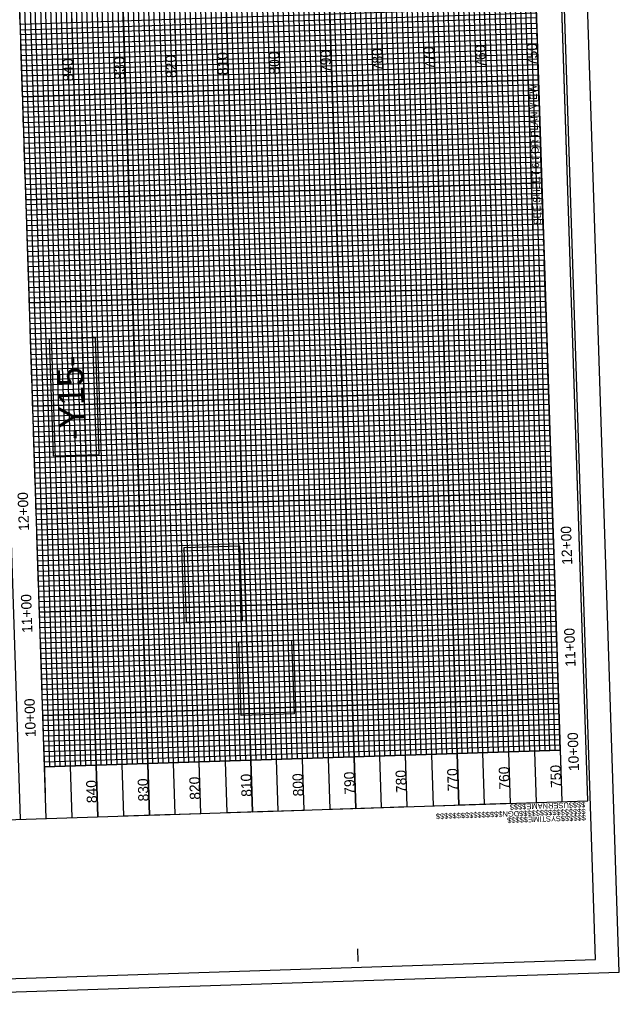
# Model space of a CAD drawing. Extents: x 1627314 to 1628469, y 762309 to 764245.
# Drawn here: x 1627888 to 1628469, y 762309 to 763268 of the extents above; entities that cross this region are included whole.
import ezdxf

# ---------------------------------------------------------------- set-up
doc = ezdxf.new("R2010")
doc.units = 0
for name, color, linetype in [('Exist Vertical Profile Horizontal Axis Label Major', 7, 'Continuous'), ('Exist Vertical Profile Vertical Axis Label', 7, 'Continuous'), ('Prop DSN Text', 7, 'Continuous'), ('Prop Grid Mask', 7, 'Continuous'), ('Sheet Data Field CELL', 7, 'Continuous'), ('Sheet DOT Grid CELL', 7, 'Continuous'), ('Sheet Layout Profile Border Port 2', 7, 'Continuous'), ('Sheet Plot Border Inside CELL', 7, 'Continuous'), ('Sheet Plot Border Outside CELL', 7, 'Continuous'), ('Sheet Profile CELL', 7, 'Continuous'), ('Sheet Profile Grid Major CELL', 7, 'Continuous'), ('Sheet Profile Grid Middle CELL', 7, 'Continuous'), ('Sheet Profile Grid Minor CELL', 7, 'Continuous')]:
    doc.layers.add(name, color=color, linetype=linetype)

msp = doc.modelspace()

# ---------------------------------------------------------------- linework, layer by layer
at = {"layer": 'Prop Grid Mask'}
for points in [[(1627891.16, 763193.83), (1627889.52, 763243.8), (1628389.25, 763260.15), (1628390.89, 763210.18)], [(1628380.89, 763209.85), (1628385.63, 763064.93), (1628395.63, 763065.25), (1628390.89, 763210.18)], [(1627965.43, 762847.15), (1627961.73, 762960.18), (1627917.01, 762958.71), (1627920.71, 762845.69)], [(1628050.07, 762684.01), (1628047.69, 762756.81), (1628101.34, 762758.56), (1628103.72, 762685.77)], [(1628102.83, 762594.05), (1628100.49, 762665.48), (1628151.84, 762667.16), (1628154.18, 762595.73)]]:
    msp.add_lwpolyline(points, close=True, dxfattribs=at)
at = {"layer": 'Sheet DOT Grid CELL'}
for p, q in [((1628263.85, 762505.65), (1628214.82, 764004.73)), ((1628313.83, 762507.28), (1628264.79, 764006.37)), ((1628363.8, 762508.92), (1628314.77, 764008)), ((1627964.01, 762495.84), (1627914.98, 763994.92)), ((1628013.99, 762497.47), (1627964.95, 763996.56)), ((1628063.96, 762499.11), (1628014.93, 763998.19)), ((1628113.93, 762500.74), (1628064.9, 763999.83)), ((1628163.91, 762502.38), (1628114.87, 764001.46)), ((1628213.88, 762504.01), (1628164.85, 764003.1)), ((1627914.04, 762494.2), (1627865.01, 763993.29)), ((1627889.52, 763243.8), (1628389.25, 763260.15)), ((1627891.16, 763193.83), (1628390.89, 763210.18)), ((1627892.79, 763143.86), (1628392.52, 763160.2)), ((1627894.43, 763093.88), (1628394.16, 763110.23)), ((1627896.06, 763043.91), (1628395.79, 763060.26)), ((1627897.69, 762993.94), (1628397.43, 763010.28)), ((1627899.33, 762943.96), (1628399.06, 762960.31)), ((1627900.96, 762893.99), (1628400.7, 762910.34)), ((1627902.6, 762844.02), (1628402.33, 762860.36)), ((1627904.23, 762794.04), (1628403.97, 762810.39)), ((1627905.87, 762744.07), (1628405.6, 762760.42)), ((1627907.5, 762694.1), (1628407.24, 762710.44)), ((1627909.14, 762644.12), (1628408.87, 762660.47)), ((1627910.77, 762594.15), (1628410.5, 762610.5)), ((1627912.41, 762544.18), (1628412.14, 762560.52))]:
    msp.add_line(p, q, dxfattribs=at)
at = {"layer": 'Sheet Layout Profile Border Port 2'}
msp.add_lwpolyline([(1627912.41, 762544.18), (1627866.64, 763943.43), (1628366.37, 763959.78), (1628412.14, 762560.52)], close=True, dxfattribs=at)
at = {"layer": 'Sheet Plot Border Inside CELL'}
msp.add_lwpolyline([(1628446.34, 762357.53), (1628391.86, 764023.14), (1627337.33, 763988.65), (1627391.81, 762323.04)], close=True, dxfattribs=at)
at = {"layer": 'Sheet Plot Border Outside CELL'}
msp.add_lwpolyline([(1628469.21, 762345.27), (1628413.63, 764044.37), (1627314.22, 764008.4), (1627369.79, 762309.31)], close=True, dxfattribs=at)
at = {"layer": 'Sheet Profile CELL'}
for p, q in [((1628364.74, 764009.75), (1628413.77, 762510.55)), ((1628438.76, 762511.37), (1628389.72, 764010.57)), ((1627889.05, 762493.39), (1627840.02, 763992.59)), ((1627914.04, 762494.2), (1627865, 763993.4)), ((1628438.76, 762511.37), (1628438.76, 762511.37)), ((1628438.76, 762511.37), (1628438.76, 762511.37)), ((1628438.76, 762511.37), (1628438.76, 762511.37)), ((1628438.76, 762511.37), (1628438.76, 762511.37)), ((1628438.76, 762511.37), (1628438.76, 762511.37)), ((1628438.76, 762511.37), (1628438.76, 762511.37)), ((1628438.76, 762511.37), (1628438.76, 762511.37)), ((1628216.24, 762355.51), (1628215.83, 762368))]:
    msp.add_line(p, q, dxfattribs=at)
msp.add_lwpolyline([(1627340.28, 763976.24), (1627389.32, 762477.04), (1628438.76, 762511.37), (1628389.72, 764010.57)], close=True, dxfattribs=at)
msp.add_lwpolyline([(1628437.53, 762548.85), (1628437.53, 762548.85)], dxfattribs=at)
at = {"layer": 'Sheet Profile Grid Major CELL'}
for p, q in [((1627891.16, 763193.83), (1627889.52, 763243.8)), ((1627894.43, 763093.88), (1627892.79, 763143.86)), ((1627897.69, 762993.94), (1627896.06, 763043.91)), ((1628413.77, 762510.55), (1628413.77, 762510.55))]:
    msp.add_line(p, q, dxfattribs=at)
for points in [[(1628164.84, 764003.21), (1628213.88, 762504.01), (1628263.85, 762505.65), (1628214.82, 764004.85)], [(1628264.79, 764006.48), (1628313.83, 762507.28), (1628313.83, 762507.28), (1628363.8, 762508.92), (1628314.76, 764008.11)], [(1628364.74, 764009.75), (1628413.77, 762510.55)], [(1627914.98, 763995.04), (1627964.01, 762495.84)], [(1627964.95, 763996.67), (1628013.99, 762497.47), (1628063.96, 762499.11), (1628014.92, 763998.31)], [(1628064.9, 763999.94), (1628113.93, 762500.74), (1628163.91, 762502.38), (1628114.87, 764001.58)], [(1627912.41, 762544.18), (1628412.14, 762560.52), (1628410.5, 762610.5), (1627910.77, 762594.15), (1627909.14, 762644.12), (1628408.87, 762660.47), (1628407.24, 762710.44), (1627907.5, 762694.1), (1627905.87, 762744.07), (1628405.6, 762760.42), (1628403.97, 762810.39), (1627904.23, 762794.04), (1627902.6, 762844.02), (1628402.33, 762860.36), (1628400.7, 762910.34), (1627900.96, 762893.99), (1627899.33, 762943.96), (1628399.06, 762960.31), (1628397.43, 763010.28), (1627897.69, 762993.94), (1627896.06, 763043.91), (1628395.79, 763060.26), (1628394.16, 763110.23), (1627894.43, 763093.88), (1627892.79, 763143.86), (1628392.52, 763160.2), (1628390.89, 763210.18), (1627891.16, 763193.83), (1627889.52, 763243.8), (1628389.25, 763260.15), (1628387.62, 763310.12)]]:
    msp.add_lwpolyline(points, dxfattribs=at)
at = {"layer": 'Sheet Profile Grid Middle CELL'}
for points in [[(1628139.86, 764002.39), (1628188.89, 762503.2), (1628238.87, 762504.83), (1628189.83, 764004.03)], [(1628239.8, 764005.66), (1628288.84, 762506.46), (1628338.81, 762508.1), (1628289.78, 764007.3)], [(1628339.75, 764008.93), (1628388.79, 762509.73)], [(1627939.03, 762495.02), (1627889.99, 763994.22)], [(1627939.96, 763995.85), (1627989, 762496.66), (1628038.97, 762498.29), (1627989.94, 763997.49)], [(1628039.91, 763999.12), (1628088.95, 762499.93), (1628138.92, 762501.56), (1628089.88, 764000.76)], [(1627913.22, 762519.19), (1627911.59, 762569.16), (1628411.32, 762585.51), (1628409.69, 762635.48), (1627909.95, 762619.14), (1627908.32, 762669.11), (1628408.05, 762685.46), (1628406.42, 762735.43), (1627906.69, 762719.08), (1627905.05, 762769.06), (1628404.78, 762785.4), (1628403.15, 762835.38), (1627903.42, 762819.03), (1627901.78, 762869), (1628401.51, 762885.35), (1628399.88, 762935.32), (1627900.15, 762918.98), (1627898.51, 762968.95), (1628398.24, 762985.3), (1628396.61, 763035.27), (1627896.88, 763018.92), (1627895.24, 763068.9), (1628394.98, 763085.24), (1628393.34, 763135.22), (1628393.34, 763135.22), (1627893.61, 763118.87), (1627891.97, 763168.84), (1628391.71, 763185.19), (1628390.07, 763235.16), (1627890.34, 763218.82), (1627888.7, 763268.79)]]:
    msp.add_lwpolyline(points, dxfattribs=at)
at = {"layer": 'Sheet Profile Grid Minor CELL'}
for p, q in [((1628292.2, 762556.6), (1628246.43, 763955.85)), ((1628251.43, 763956.02), (1628297.2, 762556.76)), ((1628302.2, 762556.93), (1628256.43, 763956.18)), ((1628261.43, 763956.34), (1628307.2, 762557.09)), ((1628317.19, 762557.42), (1628271.42, 763956.67)), ((1628276.42, 763956.83), (1628322.19, 762557.58)), ((1628327.18, 762557.75), (1628281.42, 763957)), ((1628286.41, 763957.16), (1628332.18, 762557.91)), ((1628342.18, 762558.24), (1628296.41, 763957.49)), ((1628301.4, 763957.65), (1628347.17, 762558.4)), ((1628352.17, 762558.56), (1628306.4, 763957.81)), ((1628311.4, 763957.98), (1628357.17, 762558.73)), ((1628367.16, 762559.05), (1628321.39, 763958.3)), ((1628326.39, 763958.47), (1628372.16, 762559.22)), ((1628377.16, 762559.38), (1628331.39, 763958.63)), ((1628336.39, 763958.8), (1628382.16, 762559.54)), ((1628392.15, 762559.87), (1628346.38, 763959.12)), ((1628351.38, 763959.29), (1628397.15, 762560.03)), ((1628402.14, 762560.2), (1628356.37, 763959.45)), ((1628407.14, 762560.36), (1628361.37, 763959.61)), ((1627951.59, 763946.21), (1627997.36, 762546.96)), ((1628002.36, 762547.12), (1627956.59, 763946.37)), ((1627961.59, 763946.54), (1628007.36, 762547.28)), ((1628017.35, 762547.61), (1627971.58, 763946.86)), ((1627976.58, 763947.03), (1628022.35, 762547.77)), ((1628027.34, 762547.94), (1627981.58, 763947.19)), ((1627986.57, 763947.35), (1628032.34, 762548.1)), ((1628042.34, 762548.43), (1627996.57, 763947.68)), ((1628001.56, 763947.84), (1628047.33, 762548.59)), ((1628052.33, 762548.75), (1628006.56, 763948.01)), ((1628011.56, 763948.17), (1628057.33, 762548.92)), ((1628067.32, 762549.25), (1628021.55, 763948.5)), ((1628026.55, 763948.66), (1628072.32, 762549.41)), ((1628077.32, 762549.57), (1628031.55, 763948.82)), ((1628036.55, 763948.99), (1628082.32, 762549.74)), ((1628092.31, 762550.06), (1628046.54, 763949.31)), ((1628051.54, 763949.48), (1628097.31, 762550.23)), ((1628102.3, 762550.39), (1628056.54, 763949.64)), ((1628061.53, 763949.8), (1628107.15, 762550.55)), ((1628117.3, 762550.88), (1628071.53, 763950.13)), ((1628076.52, 763950.3), (1628122.29, 762551.04)), ((1628127.29, 762551.21), (1628081.52, 763950.46)), ((1628086.52, 763950.62), (1628132.29, 762551.37)), ((1628142.28, 762551.7), (1628096.51, 763950.95)), ((1628101.51, 763951.11), (1628147.28, 762551.86)), ((1628152.28, 762552.02), (1628106.51, 763951.28)), ((1628111.51, 763951.44), (1628157.28, 762552.19)), ((1628167.27, 762552.51), (1628121.5, 763951.77)), ((1628126.5, 763951.93), (1628172.27, 762552.68)), ((1628177.26, 762552.84), (1628131.5, 763952.09)), ((1628136.49, 763952.26), (1628182.26, 762553)), ((1628192.26, 762553.33), (1628146.49, 763952.58)), ((1628151.48, 763952.75), (1628197.25, 762553.5)), ((1628202.25, 762553.66), (1628156.48, 763952.91)), ((1628161.48, 763953.07), (1628207.25, 762553.82)), ((1628217.24, 762554.15), (1628171.47, 763953.4)), ((1628176.47, 763953.56), (1628222.24, 762554.31)), ((1628227.24, 762554.48), (1628181.47, 763953.73)), ((1628186.47, 763953.89), (1628232.24, 762554.64)), ((1628242.23, 762554.97), (1628196.46, 763954.22)), ((1628201.46, 763954.38), (1628247.23, 762555.13)), ((1628252.22, 762555.29), (1628206.46, 763954.55)), ((1628211.45, 763954.71), (1628257.22, 762555.46)), ((1628267.22, 762555.78), (1628221.45, 763955.04)), ((1628226.44, 763955.2), (1628272.21, 762555.95)), ((1628277.21, 762556.11), (1628231.44, 763955.36)), ((1628236.44, 763955.53), (1628282.21, 762556.27)), ((1627917.4, 762544.34), (1627871.63, 763943.59)), ((1627876.63, 763943.76), (1627922.4, 762544.5)), ((1627927.4, 762544.67), (1627881.63, 763943.92)), ((1627886.63, 763944.08), (1627932.4, 762544.83)), ((1627942.39, 762545.16), (1627896.62, 763944.41)), ((1627901.62, 763944.57), (1627947.39, 762545.32)), ((1627952.38, 762545.49), (1627906.62, 763944.74)), ((1627911.61, 763944.9), (1627957.38, 762545.65)), ((1627967.38, 762545.98), (1627921.61, 763945.23)), ((1627926.6, 763945.39), (1627972.37, 762546.14)), ((1627977.37, 762546.3), (1627931.6, 763945.55)), ((1627936.6, 763945.72), (1627982.37, 762546.47)), ((1627992.36, 762546.79), (1627946.59, 763946.05))]:
    msp.add_line(p, q, dxfattribs=at)
for points in [[(1628388.6, 763280.14), (1627888.87, 763263.79), (1627888.54, 763273.79)], [(1627895.08, 763073.89), (1628394.81, 763090.24), (1628394.65, 763095.24), (1627894.92, 763078.89), (1627894.75, 763083.89), (1628394.49, 763100.24), (1628394.32, 763105.23), (1627894.59, 763088.89), (1627894.26, 763098.88), (1628393.99, 763115.23), (1628393.83, 763120.22), (1627894.1, 763103.88), (1627893.94, 763108.88), (1628393.67, 763125.22), (1628393.5, 763130.22), (1627893.77, 763113.87), (1627893.44, 763123.87), (1628393.18, 763140.21), (1628393.01, 763145.21), (1627893.28, 763128.87), (1627893.12, 763133.86), (1628392.85, 763150.21), (1628392.69, 763155.21), (1627892.95, 763138.86), (1627892.63, 763148.85), (1628392.36, 763165.2), (1628392.2, 763170.2), (1627892.46, 763153.85), (1627892.3, 763158.85), (1628392.03, 763175.2), (1628391.87, 763180.19), (1627892.14, 763163.85), (1627891.81, 763173.84), (1628391.54, 763190.19), (1628391.38, 763195.18), (1627891.65, 763178.84), (1627891.48, 763183.84), (1628391.22, 763200.18), (1628391.05, 763205.18), (1627891.32, 763188.83), (1627890.99, 763198.83), (1628390.73, 763215.17), (1628390.73, 763215.17), (1628390.56, 763220.17), (1627890.83, 763203.83), (1627890.67, 763208.82), (1628390.4, 763225.17), (1628390.24, 763230.17), (1627890.5, 763213.82), (1627890.18, 763223.81), (1628389.91, 763240.16), (1628389.74, 763245.16), (1627890.01, 763228.81), (1627889.85, 763233.81), (1628389.58, 763250.16), (1628389.42, 763255.15), (1627889.69, 763238.81), (1627889.36, 763248.8), (1628389.09, 763265.15), (1628388.93, 763270.14), (1627889.19, 763253.8), (1627889.03, 763258.8), (1628388.76, 763275.14)], [(1628405.11, 762775.41), (1628404.95, 762780.41), (1627905.21, 762764.06), (1627904.89, 762774.06), (1628404.62, 762790.4), (1628404.46, 762795.4), (1627904.72, 762779.05), (1627904.56, 762784.05), (1628404.29, 762800.4), (1628404.13, 762805.39), (1627904.4, 762789.05), (1627904.07, 762799.04), (1628403.8, 762815.39), (1628403.64, 762820.39), (1627903.91, 762804.04), (1627903.74, 762809.04), (1628403.48, 762825.38), (1628403.31, 762830.38), (1627903.58, 762814.03), (1627903.25, 762824.03), (1628402.99, 762840.37), (1628402.82, 762845.37), (1627903.09, 762829.03), (1627902.93, 762834.02), (1628402.66, 762850.37), (1628402.49, 762855.37), (1627902.76, 762839.02), (1627902.44, 762849.01), (1628402.17, 762865.36), (1628402, 762870.36), (1627902.27, 762854.01), (1627902.11, 762859.01), (1628401.84, 762875.36), (1628401.68, 762880.35), (1627901.94, 762864.01), (1627901.62, 762874), (1628401.35, 762890.35), (1628401.19, 762895.35), (1627901.45, 762879), (1627901.29, 762884), (1628401.02, 762900.34), (1628400.86, 762905.34), (1627901.13, 762888.99), (1627900.8, 762898.99), (1628400.53, 762915.33), (1628400.37, 762920.33), (1627900.64, 762903.99), (1627900.47, 762908.98), (1628400.21, 762925.33), (1628400.04, 762930.33), (1627900.31, 762913.98), (1627899.98, 762923.97), (1628399.72, 762940.32), (1628399.55, 762945.32), (1627899.82, 762928.97), (1627899.66, 762933.97), (1628399.39, 762950.32), (1628399.23, 762955.31), (1627899.49, 762938.97), (1627899.17, 762948.96), (1628398.9, 762965.31), (1628398.74, 762970.31), (1627899, 762953.96), (1627898.84, 762958.96), (1628398.57, 762975.3), (1628398.41, 762980.3), (1627898.68, 762963.95), (1627898.35, 762973.95), (1628398.08, 762990.29), (1628397.92, 762995.29), (1627898.19, 762978.95), (1627898.02, 762983.94), (1628397.75, 763000.29), (1628397.59, 763005.29), (1627897.86, 762988.94), (1627897.53, 762998.93), (1628397.26, 763015.28), (1628397.1, 763020.28), (1627897.37, 763003.93), (1627897.2, 763008.93), (1628396.94, 763025.28), (1628396.77, 763030.27), (1627897.04, 763013.93), (1627896.71, 763023.92), (1628396.45, 763040.27), (1628396.28, 763045.26), (1627896.55, 763028.92), (1627896.39, 763033.92), (1628396.12, 763050.26), (1628395.96, 763055.26), (1627896.22, 763038.91), (1627895.9, 763048.91), (1628395.63, 763065.25), (1628395.47, 763070.25), (1627895.73, 763053.91), (1627895.57, 763058.9), (1628395.3, 763075.25), (1628395.14, 763080.25), (1627895.41, 763063.9), (1627895.08, 763073.89)], [(1627912.41, 762544.18), (1627912.24, 762549.18), (1628411.98, 762565.52), (1628411.81, 762570.52), (1627912.08, 762554.17), (1627911.92, 762559.17), (1628411.65, 762575.52), (1628411.49, 762580.51), (1627911.75, 762564.17), (1627911.43, 762574.16), (1628411.16, 762590.51), (1628410.99, 762595.51), (1627911.26, 762579.16), (1627911.1, 762584.16), (1628410.83, 762600.5), (1628410.67, 762605.5), (1628410.34, 762615.49), (1628410.18, 762620.49), (1627910.44, 762604.15), (1627910.28, 762609.14), (1628410.01, 762625.49), (1628409.85, 762630.49), (1627910.12, 762614.14), (1627909.79, 762624.14), (1628409.52, 762640.48), (1628409.36, 762645.48), (1627909.63, 762629.13), (1627909.46, 762634.13), (1628409.2, 762650.48), (1628409.03, 762655.47), (1627909.3, 762639.13), (1627908.97, 762649.12), (1628408.71, 762665.47), (1628408.54, 762670.47), (1627908.81, 762654.12), (1627908.65, 762659.12), (1628408.38, 762675.46), (1628408.22, 762680.46), (1627908.48, 762664.11), (1627908.16, 762674.11), (1628407.89, 762690.45), (1628407.73, 762695.45), (1627907.99, 762679.11), (1627907.83, 762684.1), (1628407.56, 762700.45), (1628407.4, 762705.45), (1627907.67, 762689.1), (1627907.34, 762699.1), (1628407.07, 762715.44), (1628406.91, 762720.44), (1627907.18, 762704.09), (1627907.01, 762709.09), (1628406.74, 762725.44), (1628406.58, 762730.43), (1627906.85, 762714.09), (1627906.52, 762724.08), (1628406.25, 762740.43), (1628406.09, 762745.43), (1627906.36, 762729.08), (1627906.19, 762734.08), (1628405.93, 762750.42), (1628405.76, 762755.42), (1627906.03, 762739.07), (1627905.7, 762749.07), (1628405.44, 762765.41), (1628405.27, 762770.41), (1627905.54, 762754.07), (1627905.38, 762759.06), (1628405.11, 762775.41)], [(1628410.67, 762605.5), (1627910.94, 762589.15), (1627910.61, 762599.15), (1628410.34, 762615.49)]]:
    msp.add_lwpolyline(points, dxfattribs=at)

# ---------------------------------------------------------------- texts
at = {"layer": 'Exist Vertical Profile Horizontal Axis Label Major'}
for s, p in [('12+00', (1627897.41, 762773.12)), ('12+00', (1628423.77, 762740.31)), ('11+00', (1627900.65, 762674.26)), ('11+00', (1628427, 762641.45)), ('10+00', (1627903.96, 762573.11)), ('10+00', (1628430.31, 762540.3))]:
    msp.add_text(s, height=10, rotation=91.87347, dxfattribs=at).set_placement(p)
at = {"layer": 'Exist Vertical Profile Vertical Axis Label'}
for s, p in [('810', (1628090.32, 763214.98)), ('800', (1628140.33, 763215.42)), ('790', (1628190.31, 763217.05)), ('780', (1628240.28, 763218.69)), ('770', (1628290.25, 763220.32)), ('760', (1628340.23, 763221.96)), ('750', (1628390.2, 763223.59)), ('840', (1627940.44, 763208.88)), ('830', (1627990.41, 763210.52)), ('820', (1628040.39, 763212.15)), ('810', (1628113.21, 762515.36)), ('800', (1628163.22, 762515.79)), ('790', (1628213.19, 762517.43)), ('780', (1628263.16, 762519.06)), ('770', (1628313.14, 762520.7)), ('760', (1628363.11, 762522.33)), ('750', (1628413.08, 762523.97)), ('840', (1627963.33, 762509.26)), ('830', (1628013.3, 762510.89)), ('820', (1628063.27, 762512.53))]:
    msp.add_text(s, height=10, rotation=91.87347, dxfattribs=at).set_placement(p)
at = {"layer": 'Prop DSN Text'}
msp.add_text('SEE SHEET 6 FOR PLAN VIEW', height=7, rotation=91.87347, dxfattribs=at).set_placement((1628393.53, 763069.77))
at = {"layer": 'Sheet Data Field CELL'}
msp.add_text('-Y15-', height=25, rotation=91.87347, dxfattribs=at).set_placement((1627951.9, 762861.55))
at = {"layer": 'Sheet Profile CELL'}
for s, p in [('$$$$USERNAME$$$$', (1628436.41, 762510.23)), ('$$$$$$$$$$$$$$$$DGN$$$$$$$$$$$$$$$$', (1628436.64, 762503.66)), ('$$$$$$SYSTIME$$$$$', (1628436.83, 762497.61))]:
    msp.add_text(s, height=5.25, rotation=181.87347, dxfattribs=at).set_placement(p)

doc.saveas('drawing.dxf')
